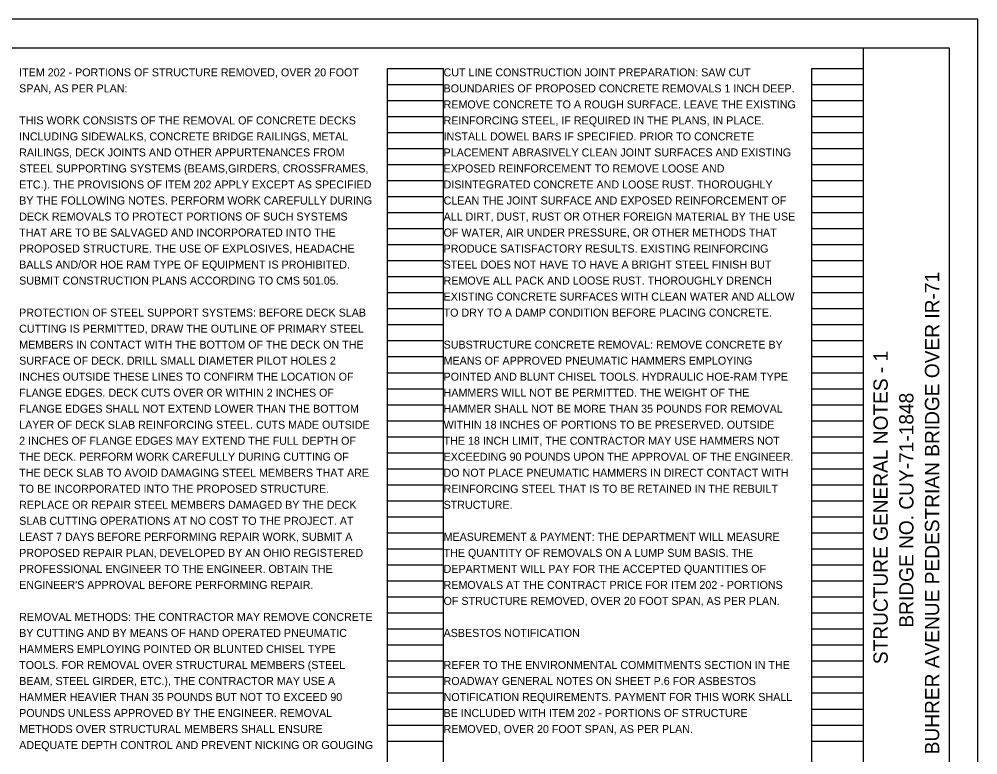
# Model space of a CAD drawing. Extents: x 0 to 34, y 0 to 22.
# Drawn here: x 17.24 to 34, y 9.14 to 22 of the extents above; entities that cross this region are included whole.
import ezdxf

# ---------------------------------------------------------------- set-up
doc = ezdxf.new("R2010")
doc.units = 0
for name, color, linetype in [('BR_P_Gen_Text', 7, 'Continuous'), ('SH_Border', 7, 'Continuous'), ('SH_Cut_Line', 7, 'Continuous'), ('SH_Data', 7, 'Continuous')]:
    doc.layers.add(name, color=color, linetype=linetype)

msp = doc.modelspace()

# ---------------------------------------------------------------- linework, layer by layer
at = {"layer": 'SH_Border'}
msp.add_line((32, 0.5), (32, 21.5), dxfattribs=at)
msp.add_lwpolyline([(1.5, 21.5), (33.5, 21.5), (33.5, 0.5), (1.5, 0.5)], close=True, dxfattribs=at)
at = {"layer": 'SH_Cut_Line'}
msp.add_lwpolyline([(0, 0), (34, 0), (34, 22), (0, 22)], close=True, dxfattribs=at)
at = {"layer": 'SH_Data'}
for p, q in [((23.68, 0.98), (23.68, 21.14)), ((23.68, 21.14), (24.66, 21.14)), ((23.68, 0.98), (23.68, 21.14)), ((23.68, 21.14), (24.66, 21.14)), ((24.66, 0.98), (24.66, 21.14)), ((24.66, 0.98), (24.66, 21.14)), ((31.1, 0.98), (31.1, 21.14)), ((31.1, 21.14), (32, 21.14)), ((31.1, 0.98), (31.1, 21.14)), ((31.1, 21.14), (32, 21.14)), ((32, 0.98), (32, 21.14)), ((32, 0.98), (32, 21.14)), ((23.68, 20.86), (24.66, 20.86)), ((23.68, 20.86), (24.66, 20.86)), ((31.1, 20.86), (32, 20.86)), ((31.1, 20.86), (32, 20.86)), ((23.68, 20.58), (24.66, 20.58)), ((23.68, 20.58), (24.66, 20.58)), ((31.1, 20.58), (32, 20.58)), ((31.1, 20.58), (32, 20.58)), ((23.68, 20.3), (24.66, 20.3)), ((23.68, 20.3), (24.66, 20.3)), ((31.1, 20.3), (32, 20.3)), ((31.1, 20.3), (32, 20.3)), ((23.68, 20.02), (24.66, 20.02)), ((23.68, 20.02), (24.66, 20.02)), ((31.1, 20.02), (32, 20.02)), ((31.1, 20.02), (32, 20.02)), ((23.68, 19.74), (24.66, 19.74)), ((23.68, 19.74), (24.66, 19.74)), ((31.1, 19.74), (32, 19.74)), ((31.1, 19.74), (32, 19.74)), ((23.68, 19.46), (24.66, 19.46)), ((23.68, 19.46), (24.66, 19.46)), ((31.1, 19.46), (32, 19.46)), ((31.1, 19.46), (32, 19.46)), ((23.68, 19.18), (24.66, 19.18)), ((23.68, 19.18), (24.66, 19.18)), ((31.1, 19.18), (32, 19.18)), ((31.1, 19.18), (32, 19.18)), ((23.68, 18.9), (24.66, 18.9)), ((23.68, 18.9), (24.66, 18.9)), ((31.1, 18.9), (32, 18.9)), ((31.1, 18.9), (32, 18.9)), ((23.68, 18.62), (24.66, 18.62)), ((23.68, 18.62), (24.66, 18.62)), ((31.1, 18.62), (32, 18.62)), ((31.1, 18.62), (32, 18.62)), ((23.68, 18.34), (24.66, 18.34)), ((23.68, 18.34), (24.66, 18.34)), ((31.1, 18.34), (32, 18.34)), ((31.1, 18.34), (32, 18.34)), ((23.68, 18.06), (24.66, 18.06)), ((23.68, 18.06), (24.66, 18.06)), ((31.1, 18.06), (32, 18.06)), ((31.1, 18.06), (32, 18.06)), ((23.68, 17.78), (24.66, 17.78)), ((23.68, 17.78), (24.66, 17.78)), ((31.1, 17.78), (32, 17.78)), ((31.1, 17.78), (32, 17.78)), ((23.68, 17.5), (24.66, 17.5)), ((23.68, 17.5), (24.66, 17.5)), ((31.1, 17.5), (32, 17.5)), ((31.1, 17.5), (32, 17.5)), ((23.68, 17.22), (24.66, 17.22)), ((23.68, 17.22), (24.66, 17.22)), ((31.1, 17.22), (32, 17.22)), ((31.1, 17.22), (32, 17.22)), ((23.68, 16.94), (24.66, 16.94)), ((23.68, 16.94), (24.66, 16.94)), ((31.1, 16.94), (32, 16.94)), ((31.1, 16.94), (32, 16.94)), ((23.68, 16.66), (24.66, 16.66)), ((23.68, 16.66), (24.66, 16.66)), ((31.1, 16.66), (32, 16.66)), ((31.1, 16.66), (32, 16.66)), ((23.68, 16.38), (24.66, 16.38)), ((23.68, 16.38), (24.66, 16.38)), ((31.1, 16.38), (32, 16.38)), ((31.1, 16.38), (32, 16.38)), ((23.68, 16.1), (24.66, 16.1)), ((23.68, 16.1), (24.66, 16.1)), ((31.1, 16.1), (32, 16.1)), ((31.1, 16.1), (32, 16.1)), ((23.68, 15.82), (24.66, 15.82)), ((23.68, 15.82), (24.66, 15.82)), ((31.1, 15.82), (32, 15.82)), ((31.1, 15.82), (32, 15.82)), ((23.68, 15.54), (24.66, 15.54)), ((23.68, 15.54), (24.66, 15.54)), ((31.1, 15.54), (32, 15.54)), ((31.1, 15.54), (32, 15.54)), ((23.68, 15.26), (24.66, 15.26)), ((23.68, 15.26), (24.66, 15.26)), ((31.1, 15.26), (32, 15.26)), ((31.1, 15.26), (32, 15.26)), ((23.68, 14.98), (24.66, 14.98)), ((23.68, 14.98), (24.66, 14.98)), ((31.1, 14.98), (32, 14.98)), ((31.1, 14.98), (32, 14.98)), ((23.68, 14.7), (24.66, 14.7)), ((23.68, 14.7), (24.66, 14.7)), ((31.1, 14.7), (32, 14.7)), ((31.1, 14.7), (32, 14.7)), ((23.68, 14.42), (24.66, 14.42)), ((23.68, 14.42), (24.66, 14.42)), ((31.1, 14.42), (32, 14.42)), ((31.1, 14.42), (32, 14.42)), ((23.68, 14.14), (24.66, 14.14)), ((23.68, 14.14), (24.66, 14.14)), ((31.1, 14.14), (32, 14.14)), ((31.1, 14.14), (32, 14.14)), ((23.68, 13.86), (24.66, 13.86)), ((23.68, 13.86), (24.66, 13.86)), ((31.1, 13.86), (32, 13.86)), ((31.1, 13.86), (32, 13.86)), ((23.68, 13.58), (24.66, 13.58)), ((23.68, 13.58), (24.66, 13.58)), ((31.1, 13.58), (32, 13.58)), ((31.1, 13.58), (32, 13.58)), ((23.68, 13.3), (24.66, 13.3)), ((23.68, 13.3), (24.66, 13.3)), ((31.1, 13.3), (32, 13.3)), ((31.1, 13.3), (32, 13.3)), ((23.68, 13.02), (24.66, 13.02)), ((23.68, 13.02), (24.66, 13.02)), ((31.1, 13.02), (32, 13.02)), ((31.1, 13.02), (32, 13.02)), ((23.68, 12.74), (24.66, 12.74)), ((23.68, 12.74), (24.66, 12.74)), ((31.1, 12.74), (32, 12.74)), ((31.1, 12.74), (32, 12.74)), ((23.68, 12.46), (24.66, 12.46)), ((23.68, 12.46), (24.66, 12.46)), ((31.1, 12.46), (32, 12.46)), ((31.1, 12.46), (32, 12.46)), ((23.68, 12.18), (24.66, 12.18)), ((23.68, 12.18), (24.66, 12.18)), ((31.1, 12.18), (32, 12.18)), ((31.1, 12.18), (32, 12.18)), ((23.68, 11.9), (24.66, 11.9)), ((23.68, 11.9), (24.66, 11.9)), ((31.1, 11.9), (32, 11.9)), ((31.1, 11.9), (32, 11.9)), ((23.68, 11.62), (24.66, 11.62)), ((23.68, 11.62), (24.66, 11.62)), ((31.1, 11.62), (32, 11.62)), ((31.1, 11.62), (32, 11.62)), ((23.68, 11.34), (24.66, 11.34)), ((23.68, 11.34), (24.66, 11.34)), ((31.1, 11.34), (32, 11.34)), ((31.1, 11.34), (32, 11.34)), ((23.68, 11.06), (24.66, 11.06)), ((23.68, 11.06), (24.66, 11.06)), ((31.1, 11.06), (32, 11.06)), ((31.1, 11.06), (32, 11.06)), ((23.68, 10.78), (24.66, 10.78)), ((23.68, 10.78), (24.66, 10.78)), ((31.1, 10.78), (32, 10.78)), ((31.1, 10.78), (32, 10.78)), ((23.68, 10.5), (24.66, 10.5)), ((23.68, 10.5), (24.66, 10.5)), ((31.1, 10.5), (32, 10.5)), ((31.1, 10.5), (32, 10.5)), ((23.68, 10.22), (24.66, 10.22)), ((23.68, 10.22), (24.66, 10.22)), ((31.1, 10.22), (32, 10.22)), ((31.1, 10.22), (32, 10.22)), ((23.68, 9.94), (24.66, 9.94)), ((23.68, 9.94), (24.66, 9.94)), ((31.1, 9.94), (32, 9.94)), ((31.1, 9.94), (32, 9.94)), ((23.68, 9.66), (24.66, 9.66)), ((23.68, 9.66), (24.66, 9.66)), ((31.1, 9.66), (32, 9.66)), ((31.1, 9.66), (32, 9.66)), ((23.68, 9.38), (24.66, 9.38)), ((23.68, 9.38), (24.66, 9.38)), ((31.1, 9.38), (32, 9.38)), ((31.1, 9.38), (32, 9.38))]:
    msp.add_line(p, q, dxfattribs=at)

# ---------------------------------------------------------------- texts
at = {"layer": 'BR_P_Gen_Text'}
for s, p in [('ITEM 202 - PORTIONS OF STRUCTURE REMOVED, OVER 20 FOOT ', (17.24, 21)), ('CUT LINE CONSTRUCTION JOINT PREPARATION: SAW CUT ', (24.66, 21)), ('SPAN, AS PER PLAN:', (17.24, 20.72)), ('BOUNDARIES OF PROPOSED CONCRETE REMOVALS 1 INCH DEEP. ', (24.66, 20.72)), ('REMOVE CONCRETE TO A ROUGH SURFACE. LEAVE THE EXISTING ', (24.66, 20.44)), ('THIS WORK CONSISTS OF THE REMOVAL OF CONCRETE DECKS ', (17.24, 20.16)), ('REINFORCING STEEL, IF REQUIRED IN THE PLANS, IN PLACE. ', (24.66, 20.16)), ('INCLUDING SIDEWALKS, CONCRETE BRIDGE RAILINGS, METAL ', (17.24, 19.88)), ('INSTALL DOWEL BARS IF SPECIFIED. PRIOR TO CONCRETE ', (24.66, 19.88)), ('RAILINGS, DECK JOINTS AND OTHER APPURTENANCES FROM ', (17.24, 19.6)), ('PLACEMENT ABRASIVELY CLEAN JOINT SURFACES AND EXISTING', (24.66, 19.6)), ('STEEL SUPPORTING SYSTEMS (BEAMS,GIRDERS, CROSSFRAMES, ', (17.24, 19.32)), ('EXPOSED REINFORCEMENT TO REMOVE LOOSE AND ', (24.66, 19.32)), ('ETC.). THE PROVISIONS OF ITEM 202 APPLY EXCEPT AS SPECIFIED ', (17.24, 19.04)), ('DISINTEGRATED CONCRETE AND LOOSE RUST. THOROUGHLY ', (24.66, 19.04)), ('BY THE FOLLOWING NOTES. PERFORM WORK CAREFULLY DURING ', (17.24, 18.76)), ('CLEAN THE JOINT SURFACE AND EXPOSED REINFORCEMENT OF ', (24.66, 18.76)), ('DECK REMOVALS TO PROTECT PORTIONS OF SUCH SYSTEMS ', (17.24, 18.48)), ('ALL DIRT, DUST, RUST OR OTHER FOREIGN MATERIAL BY THE USE ', (24.66, 18.48)), ('THAT ARE TO BE SALVAGED AND INCORPORATED INTO THE ', (17.24, 18.2)), ('OF WATER, AIR UNDER PRESSURE, OR OTHER METHODS THAT ', (24.66, 18.2)), ('PROPOSED STRUCTURE. THE USE OF EXPLOSIVES, HEADACHE ', (17.24, 17.92)), ('PRODUCE SATISFACTORY RESULTS. EXISTING REINFORCING ', (24.66, 17.92)), ('BALLS AND/OR HOE RAM TYPE OF EQUIPMENT IS PROHIBITED. ', (17.24, 17.64)), ('STEEL DOES NOT HAVE TO HAVE A BRIGHT STEEL FINISH BUT ', (24.66, 17.64)), ('SUBMIT CONSTRUCTION PLANS ACCORDING TO CMS 501.05.', (17.24, 17.36)), ('REMOVE ALL PACK AND LOOSE RUST. THOROUGHLY DRENCH ', (24.66, 17.36)), ('EXISTING CONCRETE SURFACES WITH CLEAN WATER AND ALLOW ', (24.66, 17.08)), ('PROTECTION OF STEEL SUPPORT SYSTEMS: BEFORE DECK SLAB ', (17.24, 16.8)), ('TO DRY TO A DAMP CONDITION BEFORE PLACING CONCRETE.', (24.66, 16.8)), ('CUTTING IS PERMITTED, DRAW THE OUTLINE OF PRIMARY STEEL ', (17.24, 16.52)), ('MEMBERS IN CONTACT WITH THE BOTTOM OF THE DECK ON THE ', (17.24, 16.24)), ('SUBSTRUCTURE CONCRETE REMOVAL: REMOVE CONCRETE BY ', (24.66, 16.24)), ('SURFACE OF DECK. DRILL SMALL DIAMETER PILOT HOLES 2 ', (17.24, 15.96)), ('MEANS OF APPROVED PNEUMATIC HAMMERS EMPLOYING ', (24.66, 15.96)), ('INCHES OUTSIDE THESE LINES TO CONFIRM THE LOCATION OF ', (17.24, 15.68)), ('POINTED AND BLUNT CHISEL TOOLS. HYDRAULIC HOE-RAM TYPE ', (24.66, 15.68)), ('FLANGE EDGES. DECK CUTS OVER OR WITHIN 2 INCHES OF ', (17.24, 15.4)), ('HAMMERS WILL NOT BE PERMITTED. THE WEIGHT OF THE ', (24.66, 15.4)), ('FLANGE EDGES SHALL NOT EXTEND LOWER THAN THE BOTTOM ', (17.24, 15.12)), ('HAMMER SHALL NOT BE MORE THAN 35 POUNDS FOR REMOVAL ', (24.66, 15.12)), ('LAYER OF DECK SLAB REINFORCING STEEL. CUTS MADE OUTSIDE ', (17.24, 14.84)), ('WITHIN 18 INCHES OF PORTIONS TO BE PRESERVED. OUTSIDE ', (24.66, 14.84)), ('2 INCHES OF FLANGE EDGES MAY EXTEND THE FULL DEPTH OF ', (17.24, 14.56)), ('THE 18 INCH LIMIT, THE CONTRACTOR MAY USE HAMMERS NOT ', (24.66, 14.56)), ('THE DECK. PERFORM WORK CAREFULLY DURING CUTTING OF ', (17.24, 14.28)), ('EXCEEDING 90 POUNDS UPON THE APPROVAL OF THE ENGINEER. ', (24.66, 14.28)), ('THE DECK SLAB TO AVOID DAMAGING STEEL MEMBERS THAT ARE ', (17.24, 14)), ('DO NOT PLACE PNEUMATIC HAMMERS IN DIRECT CONTACT WITH ', (24.66, 14)), ('TO BE INCORPORATED INTO THE PROPOSED STRUCTURE. ', (17.24, 13.72)), ('REINFORCING STEEL THAT IS TO BE RETAINED IN THE REBUILT ', (24.66, 13.72)), ('REPLACE OR REPAIR STEEL MEMBERS DAMAGED BY THE DECK ', (17.24, 13.44)), ('STRUCTURE.', (24.66, 13.44)), ('SLAB CUTTING OPERATIONS AT NO COST TO THE PROJECT. AT ', (17.24, 13.16)), ('LEAST 7 DAYS BEFORE PERFORMING REPAIR WORK, SUBMIT A ', (17.24, 12.88)), ('MEASUREMENT & PAYMENT: THE DEPARTMENT WILL MEASURE ', (24.66, 12.88)), ('PROPOSED REPAIR PLAN, DEVELOPED BY AN OHIO REGISTERED ', (17.24, 12.6)), ('THE QUANTITY OF REMOVALS ON A LUMP SUM BASIS. THE ', (24.66, 12.6)), ('PROFESSIONAL ENGINEER TO THE ENGINEER. OBTAIN THE ', (17.24, 12.32)), ('DEPARTMENT WILL PAY FOR THE ACCEPTED QUANTITIES OF ', (24.66, 12.32)), ("ENGINEER'S APPROVAL BEFORE PERFORMING REPAIR.", (17.24, 12.04)), ('REMOVALS AT THE CONTRACT PRICE FOR ITEM 202 - PORTIONS ', (24.66, 12.04)), ('OF STRUCTURE REMOVED, OVER 20 FOOT SPAN, AS PER PLAN.', (24.66, 11.76)), ('REMOVAL METHODS: THE CONTRACTOR MAY REMOVE CONCRETE ', (17.24, 11.48)), ('BY CUTTING AND BY MEANS OF HAND OPERATED PNEUMATIC ', (17.24, 11.2)), ('ASBESTOS NOTIFICATION', (24.66, 11.2)), ('HAMMERS EMPLOYING POINTED OR BLUNTED CHISEL TYPE ', (17.24, 10.92)), ('TOOLS. FOR REMOVAL OVER STRUCTURAL MEMBERS (STEEL ', (17.24, 10.64)), ('REFER TO THE ENVIRONMENTAL COMMITMENTS SECTION IN THE ', (24.66, 10.64)), ('BEAM, STEEL GIRDER, ETC.), THE CONTRACTOR MAY USE A ', (17.24, 10.36)), ('ROADWAY GENERAL NOTES ON SHEET P.6 FOR ASBESTOS ', (24.66, 10.36)), ('HAMMER HEAVIER THAN 35 POUNDS BUT NOT TO EXCEED 90 ', (17.24, 10.08)), ('NOTIFICATION REQUIREMENTS. PAYMENT FOR THIS WORK SHALL ', (24.66, 10.08)), ('POUNDS UNLESS APPROVED BY THE ENGINEER. REMOVAL ', (17.24, 9.8)), ('BE INCLUDED WITH ITEM 202 - PORTIONS OF STRUCTURE ', (24.66, 9.8)), ('METHODS OVER STRUCTURAL MEMBERS SHALL ENSURE ', (17.24, 9.52)), ('REMOVED, OVER 20 FOOT SPAN, AS PER PLAN.', (24.66, 9.52)), ('ADEQUATE DEPTH CONTROL AND PREVENT NICKING OR GOUGING ', (17.24, 9.24))]:
    msp.add_text(s, height=0.14, dxfattribs=at).set_placement(p)
at = {"layer": 'SH_Data'}
for s, p in [('BUHRER AVENUE PEDESTRIAN BRIDGE OVER IR-71', (33.325, 9.148)), ('STRUCTURE GENERAL NOTES - 1', (32.425, 10.724)), ('BRIDGE NO. CUY-71-1848', (32.875, 11.363))]:
    msp.add_text(s, height=0.25, rotation=90, dxfattribs=at).set_placement(p)

doc.saveas('drawing.dxf')
